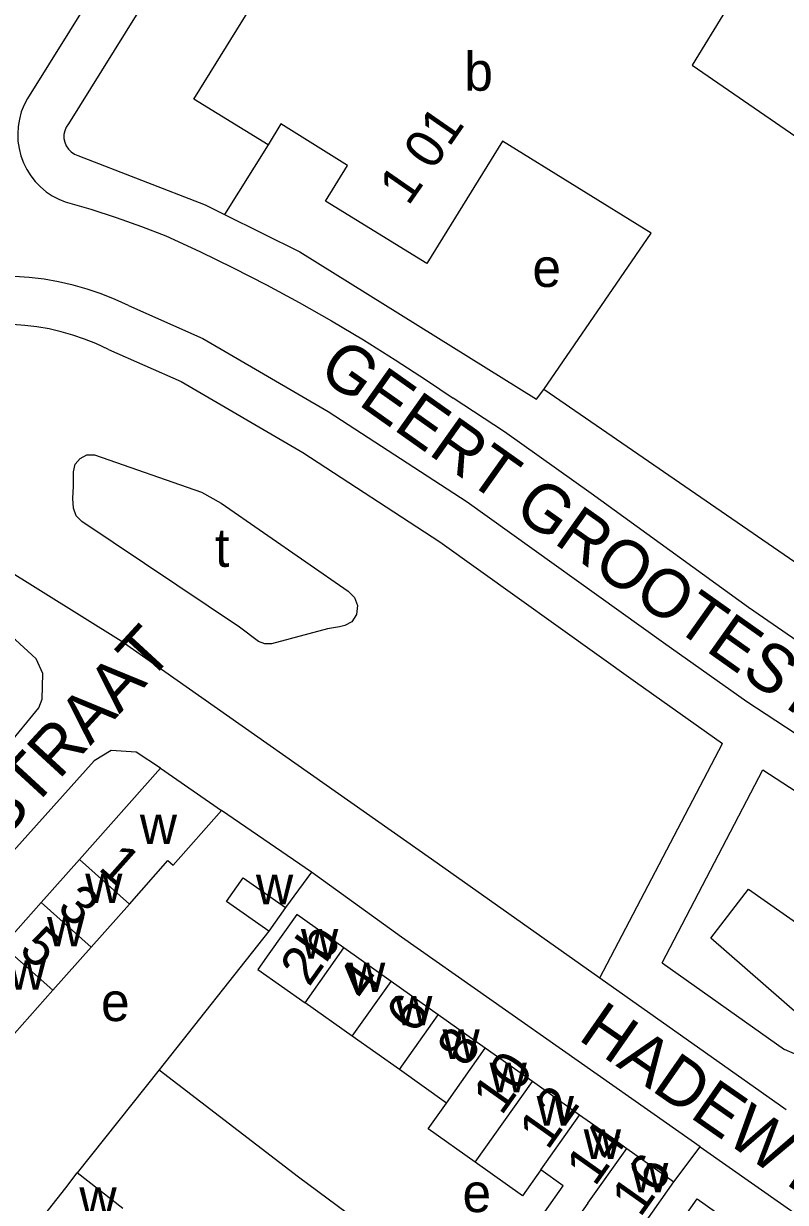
# Model space of a CAD drawing. Extents: x 162804 to 165059, y 381530 to 382901.
# Drawn here: x 162938.5 to 163017.6, y 382013.3 to 382135.7 of the extents above; entities that cross this region are included whole.
import ezdxf

# ---------------------------------------------------------------- set-up
doc = ezdxf.new("R2010")
doc.units = 0
for name, color, linetype in [('BLT_Basislijn', 7, 'Continuous'), ('BLT_Bebouwing', 7, 'Continuous'), ('BLT_Centroide', 7, 'Continuous'), ('BLT_Huisnummer', 7, 'Continuous'), ('BLT_Huisnummer_ tussenligend', 7, 'Continuous'), ('BLT_Huisnummer_reeks', 7, 'Continuous'), ('BLT_Onderverdeling_panden', 7, 'Continuous'), ('BLT_Straatnaam', 7, 'Continuous')]:
    doc.layers.add(name, color=color, linetype=linetype)

msp = doc.modelspace()

# ---------------------------------------------------------------- linework, layer by layer
at = {"layer": 'BLT_Basislijn'}
for p, q in [((162983.56, 382199.62), (162938.92, 382127.95)), ((162958.47, 382149.88), (162943.16, 382125.31)), ((162963.89, 382123.14), (162959.38, 382115.89)), ((163022.96, 382068.7), (163013.79, 382075.08)), ((162998.35, 382036.61), (163011.06, 382060.97)), ((163004.81, 382038.17), (163015.27, 382058.23)), ((162968.39, 382047.61), (162959.05, 382053.98)), ((162980.88, 382048.98), (162998.35, 382036.61)), ((162968.39, 382047.61), (162965.69, 382043.91)), ((162963.96, 382041.46), (162952.58, 382027.08)), ((163004.81, 382038.17), (163017.52, 382029.19)), ((162998.35, 382036.61), (163017.7, 382022.93)), ((162952.58, 382027.08), (162944.09, 382016.36)), ((163006.03, 382015.43), (163008.76, 382019.07))]:
    msp.add_line(p, q, dxfattribs=at)
for points in [[(162938.92, 382127.95), (162938.56, 382127.27), (162938.28, 382126.55), (162938.08, 382125.8), (162937.95, 382125.04), (162937.9, 382124.27), (162937.93, 382123.5), (162938.05, 382122.74), (162938.24, 382121.99), (162938.5, 382121.27), (162938.84, 382120.58), (162939.26, 382119.92), (162939.73, 382119.32), (162940.27, 382118.76), (162940.86, 382118.26), (162941.49, 382117.83), (162942.18, 382117.47), (162942.82, 382117.2)], [(162943.16, 382125.31), (162942.93, 382124.97), (162942.78, 382124.59), (162942.7, 382124.2), (162942.7, 382123.79), (162942.78, 382123.39), (162942.93, 382123.02), (162943.16, 382122.68), (162943.45, 382122.39), (162943.79, 382122.17), (162944.14, 382122.02)], [(162944.14, 382122.02), (162957.36, 382116.89), (162959.38, 382115.89)], [(162942.82, 382117.2), (162945.49, 382116.43), (162948.14, 382115.58), (162950.76, 382114.65), (162953.29, 382113.68)], [(162959.38, 382115.89), (162967.18, 382112.03), (162991.78, 382096.7), (162992.52, 382097.73)], [(162953.29, 382113.68), (162956.8, 382112.06), (162960.28, 382110.36), (162963.72, 382108.59), (162967.12, 382106.75), (162970.49, 382104.84), (162973.82, 382102.86), (162977.1, 382100.81), (162980.34, 382098.7), (162983.11, 382096.81)], [(162949.4, 382106.43), (162948.01, 382107.08), (162946.58, 382107.65), (162945.13, 382108.15), (162943.65, 382108.57), (162942.15, 382108.91), (162940.64, 382109.18), (162939.11, 382109.36), (162937.58, 382109.47), (162936.04, 382109.5), (162934.51, 382109.44), (162932.97, 382109.31), (162931.45, 382109.1), (162929.94, 382108.81), (162928.45, 382108.44), (162926.98, 382107.99), (162926.13, 382107.69)], [(162949.4, 382106.43), (162957.14, 382103), (162970.13, 382095.43), (162984.56, 382086.04), (163004.95, 382071.43), (163013.61, 382065.3)], [(162947.34, 382101.88), (162946.02, 382102.48), (162944.84, 382102.96), (162943.63, 382103.37), (162942.4, 382103.72), (162941.16, 382104.01), (162939.9, 382104.23), (162938.63, 382104.38), (162937.36, 382104.47), (162936.08, 382104.5), (162934.81, 382104.45), (162933.54, 382104.34), (162932.27, 382104.16), (162931.02, 382103.92), (162929.78, 382103.61), (162926.15, 382102.56)], [(162947.34, 382101.88), (162954.86, 382098.54), (162967.5, 382091.17), (162981.74, 382081.91), (163002.04, 382067.36), (163011.06, 382060.97)], [(163013.79, 382075.08), (162997.45, 382086.91), (162988.43, 382093.32), (162983.11, 382096.81)], [(162915.66, 382092.18), (162948.66, 382071.61), (162980.88, 382048.98)], [(162907.6, 382027.35), (162907.8, 382027.7), (162909.42, 382029.33), (162918.85, 382040.34), (162936.8, 382060.63), (162940.11, 382064.67), (162940.46, 382065.55), (162940.51, 382068.21), (162939.83, 382069.75), (162937.66, 382071.73), (162920.14, 382082.1), (162909.94, 382088.71)], [(163013.61, 382065.3), (163024.74, 382058.01), (163033.59, 382052.6), (163051.63, 382042.67), (163072.01, 382032.56), (163088.97, 382023.89)], [(162952.73, 382058.39), (162950.2, 382060.04), (162947.6, 382060.24), (162945.85, 382059.17), (162917.07, 382027.1), (162916.84, 382023.91), (162917.94, 382021.92), (162919.34, 382020.66), (162924.61, 382016.72), (162925.66, 382015.7), (162927.68, 382014.31), (162935.65, 382008.02), (162936.61, 382007.27)], [(163015.27, 382058.23), (163022.07, 382053.79), (163031.07, 382048.27), (163049.31, 382038.24), (163069.76, 382028.09), (163086.74, 382019.42)], [(163008.76, 382019.07), (163005.26, 382021.53), (162977.74, 382040.83), (162968.39, 382047.61)], [(163072.1, 382008.69), (163021.58, 382030.69), (163021.26, 382030.8), (163020.99, 382031), (163009.87, 382040.75), (163013.79, 382045.83), (163033.17, 382032.21), (163033.55, 382032.01), (163033.92, 382031.91), (163034.35, 382031.89), (163034.73, 382031.97), (163040.77, 382033.98), (163041.38, 382034.11), (163042.05, 382034.13), (163042.72, 382034.02), (163043.3, 382033.81), (163062, 382020.7), (163063.13, 382020.31), (163064.33, 382020.39), (163066.27, 382020.84), (163067.69, 382020.94), (163069.06, 382020.59), (163092.61, 382008.67)], [(163083.72, 381982.26), (163080.85, 381987.02), (163070.82, 382005.91), (163070.76, 382005.99), (163070.7, 382006.03), (163017.52, 382029.19)], [(162952.58, 382027.08), (162967.07, 382015.96), (162990.08, 381998.88), (162991.04, 381998.28)], [(163008.76, 382019.07), (163083.58, 381966.59), (163084.55, 381965.91)]]:
    msp.add_lwpolyline(points, dxfattribs=at)
msp.add_lwpolyline([(162960.93, 382073.02), (162944.56, 382084.01), (162943.96, 382084.6), (162943.71, 382085.4), (162943.64, 382086.41), (162943.68, 382087.67), (162943.69, 382089.18), (162943.88, 382089.96), (162944.38, 382090.57), (162945.09, 382090.92), (162945.89, 382090.94), (162957, 382087.05), (162959.01, 382085.93), (162972.2, 382076.78), (162972.87, 382076.13), (162973.18, 382075.28), (162973.07, 382074.35), (162972.58, 382073.59), (162971.88, 382073.21), (162971.31, 382073.08), (162970.07, 382072.86), (162964.24, 382071.3), (162963.55, 382071.29), (162962.91, 382071.55)], close=True, dxfattribs=at)
at = {"layer": 'BLT_Bebouwing'}
for p, q in [((162952.73, 382058.39), (162944.33, 382048.92)), ((162952.73, 382058.39), (162959.05, 382053.98)), ((162944.33, 382048.92), (162940.34, 382044.43)), ((162940.34, 382044.43), (162936.36, 382039.94)), ((162945.54, 382039.82), (162949.5, 382044.28)), ((162965.69, 382043.91), (162963.96, 382041.46)), ((162941.55, 382035.33), (162945.54, 382039.82)), ((162976.67, 382036.25), (162971.77, 382039.72)), ((162981.56, 382032.78), (162976.67, 382036.25)), ((162937.57, 382030.83), (162941.55, 382035.33)), ((162972.64, 382030.56), (162967.74, 382034.03)), ((162986.45, 382029.31), (162981.56, 382032.78)), ((162977.53, 382027.09), (162972.64, 382030.56)), ((162991.35, 382025.84), (162986.45, 382029.31)), ((162982.43, 382023.62), (162977.53, 382027.09)), ((162996.24, 382022.37), (162991.35, 382025.84)), ((163000, 382019.71), (162996.24, 382022.37)), ((163000, 382019.71), (163001.14, 382018.9)), ((163001.14, 382018.9), (163006.03, 382015.43)), ((162948.82, 382012.66), (162944.09, 382016.36))]:
    msp.add_line(p, q, dxfattribs=at)
for points in [[(163014.6, 382178.89), (163011.07, 382161.23), (163022.77, 382158.87), (163022.84, 382159.19), (163050.3, 382153.71), (163046.79, 382136.34), (163032.5, 382139.24), (163032.61, 382139.53), (163015.07, 382143.06), (163007.93, 382131.41)], [(162956.2, 382127.87), (162966.81, 382145.03), (162965.6, 382145.78), (162965.51, 382145.62), (162964.05, 382146.29)], [(163007.93, 382131.41), (163046.09, 382105.14), (163047.74, 382107.54), (163055.8, 382104.7), (163051.71, 382093.08)], [(162963.89, 382123.14), (162956.2, 382127.87)], [(162992.52, 382097.73), (163003.67, 382113.96), (162988.24, 382123.51), (162980.38, 382110.79), (162969.86, 382117.27), (162972.14, 382120.97), (162965.23, 382125.31), (162963.89, 382123.14)], [(163026.67, 382074.22), (162992.52, 382097.73)], [(162949.5, 382044.28), (162953.5, 382048.8), (162954.04, 382048.33), (162959.05, 382053.98)], [(162963.96, 382041.46), (162959.58, 382044.56), (162961.32, 382047.01), (162965.69, 382043.91)], [(162971.77, 382039.72), (162966.88, 382043.18), (162963.99, 382039.1), (162962.85, 382037.5), (162967.74, 382034.03)], [(162985.41, 382017.46), (162980.52, 382020.93), (162982.43, 382023.62)], [(162992.21, 382016.68), (162990.31, 382013.99), (162985.41, 382017.46)], [(162997.11, 382013.21), (162995.2, 382010.52), (162992.64, 382012.33), (162994.55, 382015.03), (162992.21, 382016.68)], [(162939.82, 382010.89), (162942.9, 382014.82), (162944.09, 382016.36)], [(163002.01, 382009.76), (163003.14, 382011.36), (163006.03, 382015.43)], [(163009.29, 382004.54), (163004.42, 382007.98), (163005.56, 382009.59), (163008.45, 382013.67), (163013.32, 382010.22)]]:
    msp.add_lwpolyline(points, dxfattribs=at)
at = {"layer": 'BLT_Onderverdeling_panden'}
for p, q in [((162944.33, 382048.92), (162949.5, 382044.28)), ((162940.34, 382044.43), (162945.54, 382039.82)), ((162936.36, 382039.94), (162941.55, 382035.33)), ((162967.74, 382034.03), (162971.77, 382039.72)), ((162972.64, 382030.56), (162976.67, 382036.25)), ((162977.53, 382027.09), (162981.56, 382032.78)), ((162982.43, 382023.62), (162986.45, 382029.31)), ((162985.41, 382017.46), (162991.35, 382025.84)), ((162992.21, 382016.68), (162996.24, 382022.37)), ((162997.11, 382013.21), (163001.14, 382018.9))]:
    msp.add_line(p, q, dxfattribs=at)

# ---------------------------------------------------------------- texts
at = {"layer": 'BLT_Centroide'}
for s, p in [('b', (162984.27, 382128.75)), ('e', (162991.34, 382108.37)), ('t', (162958.39, 382079.3)), ('w', (162950.58, 382050.51)), ('w', (162944.91, 382044.38)), ('w', (162962.64, 382044.25)), ('w', (162940.95, 382039.88)), ('w', (162967.31, 382038.61)), ('w', (162936.96, 382035.38)), ('w', (162972.2, 382035.14)), ('e', (162946.55, 382032.13)), ('w', (162977.09, 382031.67)), ('w', (162982, 382028.2)), ('w', (162986.89, 382024.73)), ('w', (162991.78, 382021.27)), ('w', (162996.67, 382017.8)), ('w', (163001.58, 382014.33)), ('e', (162984.08, 382012.29)), ('w', (162944.31, 382011.78))]:
    msp.add_text(s, height=4, dxfattribs=at).set_placement(p)
at = {"layer": 'BLT_Huisnummer'}
for s, rotation, p in [('1', 318.413, (162946.15, 382047.92)), ('5', 318.4137, (162937.9, 382039.32)), ('2b', 54.6879, (162968.15, 382035.6)), ('4', 54.6891, (162974.05, 382034.06)), ('8', 54.6921, (162984.43, 382027.18)), ('12', 54.7075, (162992.93, 382018.63)), ('16', 54.7141, (163002.53, 382011.64))]:
    msp.add_text(s, height=4, rotation=rotation, dxfattribs=at).set_placement(p)
at = {"layer": 'BLT_Huisnummer_ tussenligend'}
for s, rotation, p in [('3', 318.413, (162941.85, 382043.69)), ('6', 54.6891, (162979.14, 382030.66)), ('10', 54.6921, (162988.13, 382022.22)), ('14', 54.7075, (162997.82, 382014.85))]:
    msp.add_text(s, height=4, rotation=rotation, dxfattribs=at).set_placement(p)
at = {"layer": 'BLT_Huisnummer_reeks'}
msp.add_text('1 01', height=4, rotation=55.2499, dxfattribs=at).set_placement((162978.45, 382116.69))
at = {"layer": 'BLT_Straatnaam'}
for s, rotation, p in [('GEERT GROOTESTRAAT', 324.6713, (162968.9, 382099.22)), ('ST LUTGARTSTRAAT', 47.3913, (162908.22, 382020.21)), ('HADEWYCHLAAN', 325.177, (162995.96, 382030.28))]:
    msp.add_text(s, height=5, rotation=rotation, dxfattribs=at).set_placement(p)

doc.saveas('drawing.dxf')
